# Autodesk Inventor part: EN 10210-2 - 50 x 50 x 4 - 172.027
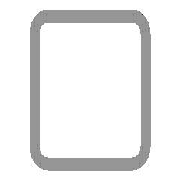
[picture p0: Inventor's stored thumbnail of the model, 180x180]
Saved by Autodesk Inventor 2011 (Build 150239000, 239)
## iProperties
IsCustomPart: 1
Created: 2010-02
Part Number: EN 10210-2 - 50 x 50 x 4 - 172.027
Material: Steel, Mild
Description: Tube 50*50*4
Document SubType Name: Modeling
Standard: DIN
Designer: PC
Standard Revision: 1997
Standards Organization: DIN
Language: en-US
Size Designation: 50 x 50 x 4
Categories: <MemberInstance><Categories><Category DisplayName="Structural Shapes" InternalName="089c4875-fa83-4c05-b084-43b9cc11f5ed" Mnemonic="GRDR"><CategoryParameter Dis
Stock Number: 50 x 50 x 4
Density: 7.86 g/cm^3
G_L: 172.027 mm
G_W: 50.000 mm
G_H: 50.000 mm
+BBAB4596-D8FD-449F-9338-D1E4F0D92D18+CUTDETAIL1: Cut
_CCFamilyMember: 15
_CCFamilyDisplayName: DIN EN 10210-2 (Square) - Tube
_FrameMemberDoc: Frame Member File
_Version: 15.0.0
_GetPNFromCC: 1
Author: PC
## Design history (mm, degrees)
node "Start plane"
node "End plane"
sketch "Sketch"
  geometry: L1 (-25, -19)-(-25, 19); L2 (-19, 25)-(19, 25); L3 (25, 19)-(25, -19); L4 (19, -25)-(-19, -25); L5 (-19, 21)-(19, 21); L6 (21, 19)-(21, -19); L7 (19, -21)-(-19, -21); L8 (-21, -19)-(-21, 19); L9 (0, 36.74)-(0, -36.74) reference; L10 (-36.74, 0)-(36.74, 0) reference; A1 r 6 centre (-19, -19) between (-25, -19) and (-19, -25); A2 r 6 centre (-19, 19) between (-19, 25) and (-25, 19); A3 r 6 centre (19, 19) between (25, 19) and (19, 25); A4 r 6 centre (19, -19) between (19, -25) and (25, -19); A5 r 2 centre (-19, 19) between (-19, 21) and (-21, 19); A6 r 2 centre (19, 19) between (21, 19) and (19, 21); A7 r 2 centre (19, -19) between (19, -21) and (21, -19); A8 r 2 centre (-19, -19) between (-21, -19) and (-19, -21)
  constraints: 16 end point, 16 point on circle, 8 centre point, 8 tangent, 4 parallel, 3 equal radius, 2 perpendicular, 7 other
  dimensions: "d7" = 6 radius of A1 (= G_IR); "d10" = 50 distance between parallel lines of L2 L4 (= G_H); "d11" = 50 distance between parallel lines of L1 L3 (= G_W); "d12" = 4 distance between parallel lines of L3 L6 (= G_T); "d15" = 25 distance between parallel lines of L2 L10 (= 0.5 x d10); "d16" = 25 distance between parallel lines of L9 L3 (= 0.5 x d11)
extrude "Body" new body sketch "Sketch" stored distance "d3" = 172.02704 (= G_L); taper "d4" = 0 deg
node "Driven Length"
  sketch "Sketch3"
    geometry: L1 (0, 0)-(10, 0) reference
    constraints: 2 end point, 1 horizontal
  workplane "Work Plane3"
  sketch "Sketch4"
    geometry: L1 (-2, -7.027)-(12, -7.027) reference; L2 (-2, 165)-(12, 165) reference
    dimensions: "d18" = 172.02704 distance between parallel lines of L1 L2 (derived)
workplane "Work Plane4"
split "Split1"
body "Solid1"
other parameters: "G_W" = 50 [user parameter; used in 1 equation term], "G_H" = 50 [user parameter; used in 1 equation term], "G_T" = 4 [user parameter; used in 1 equation term], "G_IR" = 6 [user parameter; used in 1 equation term], "G_L" = 172.02704 (= d18) [user parameter; used in 1 equation term], "G_OFFSET_START" = 7.02704 [user parameter; used in 1 equation term], "G_OFFSET_END" = 0 [user parameter; used in 1 equation term], "d13" = -7.02704 (= -G_OFFSET_START), "d14" = 165 (= G_OFFSET_END + B_L), "B_L" = 165 [user parameter; used in 1 equation term], "d17" = 90 deg
